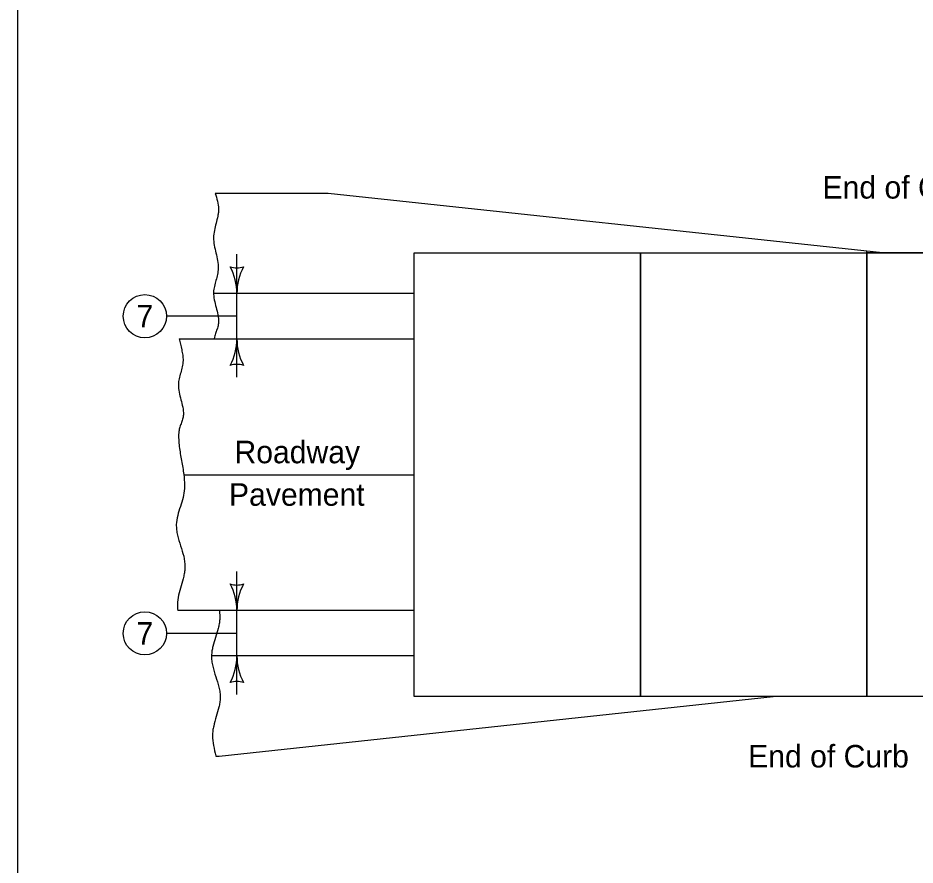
# Model space of a CAD drawing. Extents: x 5546 to 81668, y 3174 to 15999.
# Drawn here: x 17333 to 17970, y 8741 to 9343 of the extents above; entities that cross this region are included whole.
import ezdxf

# ---------------------------------------------------------------- set-up
doc = ezdxf.new("R2010")
doc.units = 0
for name, color, linetype in [('Level 61', 7, 'Continuous'), ('PS_BOLT', 7, 'Continuous'), ('PS_DIM', 7, 'Continuous'), ('Table Border', 7, 'Continuous')]:
    doc.layers.add(name, color=color, linetype=linetype)

msp = doc.modelspace()

# ---------------------------------------------------------------- linework, layer by layer
at = {"layer": 'Level 61'}
msp.add_lwpolyline([(17332.52, 9944.02), (20467.53, 9944.02), (20467.53, 7924.02), (17332.52, 7924.02)], close=True, dxfattribs=at)
at = {"layer": 'PS_DIM'}
for p, q in [((17553, 9217.99), (17472.63, 9217.99)), ((17946.65, 9175.72), (17553, 9217.99)), ((17488.06, 9087.36), (17488.06, 9174.78)), ((17613.88, 9146.9), (17471.46, 9146.9)), ((17458.59, 9130.77), (17438.03, 9130.77)), ((17488.06, 9130.77), (17458.59, 9130.77)), ((17447.13, 9114.73), (17613.88, 9114.73)), ((17450.33, 9018.22), (17613.88, 9018.22)), ((17488.06, 8862.17), (17488.06, 8949.6)), ((17613.88, 8921.71), (17445.98, 8921.71)), ((17458.59, 8905.58), (17438.03, 8905.58)), ((17488.06, 8905.58), (17458.59, 8905.58)), ((17613.88, 8889.54), (17470.02, 8889.54)), ((17475.42, 8818.46), (17868.97, 8860.72))]:
    msp.add_line(p, q, dxfattribs=at)
for points in [[(17613.88, 8860.72), (17613.88, 9175.72), (17774.73, 9175.72), (17774.73, 8860.72)], [(17868.97, 8860.73), (17868.97, 8860.72), (17774.73, 8860.72), (17774.73, 9175.72), (17935.58, 9175.72), (17935.58, 8860.73)], [(17935.58, 8860.73), (17935.58, 9175.72), (17946.65, 9175.72), (17946.65, 9175.72), (18096.43, 9175.72), (18096.43, 8864.74), (18055.7, 8864.74), (18055.7, 8860.73)]]:
    msp.add_lwpolyline(points, close=True, dxfattribs=at)
for centre in [(17422.67, 9130.77), (17422.67, 8905.58)]:
    msp.add_circle(centre, 15.36, dxfattribs=at)
for centre, radius, start, end in [((17488.06, 9180.59), 15.52, 252.26665, 287.73335), ((17447.88, 9146.9), 40.18, 0, 28.07249), ((17528.23, 9146.9), 40.18, 151.92751, 180), ((17447.88, 9114.73), 40.18, 331.92751, 0), ((17528.23, 9114.73), 40.18, 180, 208.07249), ((17488.06, 9081.05), 15.52, 72.26665, 107.73335), ((17488.06, 8955.4), 15.52, 252.26665, 287.73335), ((17447.88, 8921.71), 40.18, 0, 28.07249), ((17528.23, 8921.71), 40.18, 151.92751, 180), ((17447.88, 8889.54), 40.18, 331.92751, 0), ((17528.23, 8889.54), 40.18, 180, 208.07249), ((17488.06, 8855.86), 15.52, 72.26665, 107.73335)]:
    msp.add_arc(centre, radius, start, end, dxfattribs=at)
at = {"layer": 'Table Border'}
for p, q in [((17935.58, 8860.72), (17935.58, 9176.91)), ((17613.88, 8860.72), (17613.88, 9175.72)), ((17613.88, 9175.72), (17774.73, 9175.72)), ((17613.88, 9146.9), (17613.88, 9175.72)), ((17613.88, 9175.72), (17946.65, 9175.72)), ((17774.73, 8860.72), (17774.73, 9175.72)), ((17774.73, 9175.72), (17935.58, 9175.72)), ((18360.8, 9175.72), (17935.58, 9175.72)), ((17613.88, 9114.73), (17613.88, 9146.9)), ((17613.88, 8860.72), (17613.88, 8889.54)), ((18283.22, 8860.73), (17613.88, 8860.73)), ((17868.97, 8860.72), (17613.88, 8860.72)), ((17473.02, 8818.46), (17475.42, 8818.46))]:
    msp.add_line(p, q, dxfattribs=at)
for points in [[(17472.63, 9217.99), (17474.2, 9212.47), (17475.03, 9206.94), (17474.88, 9204.39), (17474.48, 9201.85), (17473.27, 9196.75), (17472.05, 9191.66), (17471.47, 9186.56), (17471.98, 9181.12), (17473.14, 9175.66), (17474.3, 9170.21), (17474.79, 9164.76), (17474.27, 9160.49), (17473.17, 9156.23), (17472.06, 9151.97), (17471.47, 9147.7), (17471.98, 9142.38), (17473.28, 9137.04), (17474.57, 9131.71), (17475.03, 9126.38), (17474.46, 9123.16), (17473.38, 9119.98), (17472.3, 9116.8), (17471.82, 9114.73)], [(17447.13, 9114.73), (17448.85, 9106.96), (17449.54, 9103.07), (17449.79, 9099.2), (17449.26, 9094.92), (17448.17, 9090.66), (17447.05, 9086.4), (17446.47, 9082.14), (17446.98, 9076.82), (17448.28, 9071.48), (17449.57, 9066.14), (17450.02, 9060.81), (17449.46, 9057.59), (17448.38, 9054.41), (17447.29, 9051.23), (17446.71, 9048.02), (17446.71, 9043.11), (17447.14, 9038.17), (17448.72, 9028.22), (17450.33, 9018.27), (17450.86, 9010.88), (17450.82, 9008.44), (17449.79, 9002.02), (17447.88, 8995.61), (17446, 8989.2), (17445.03, 8982.77), (17445.21, 8979.02), (17445.88, 8975.27), (17448.05, 8967.76), (17450.25, 8960.26), (17451.18, 8952.76), (17450.9, 8949.41), (17450.26, 8946.07), (17448.41, 8939.39), (17446.59, 8932.7), (17445.75, 8926), (17445.98, 8921.71)], [(17475.7, 8921.71), (17475.82, 8915.49), (17475.47, 8912.27), (17474.79, 8909.06), (17472.88, 8902.65), (17471, 8896.24), (17470.33, 8893.06), (17470.14, 8891.43), (17470.03, 8889.81), (17470.21, 8886.06), (17470.88, 8882.31), (17473.06, 8874.81), (17475.25, 8867.3), (17475.98, 8863.58), (17476.14, 8861.69), (17476.18, 8859.8), (17475.9, 8856.46), (17475.27, 8853.11), (17473.41, 8846.43), (17471.59, 8839.74), (17470.95, 8836.41), (17470.81, 8834.72), (17470.76, 8833.04), (17471.45, 8825.84), (17472.99, 8818.6), (17473.02, 8818.46)]]:
    msp.add_spline(points, degree=3, dxfattribs=at)

# ---------------------------------------------------------------- texts
at = {"layer": 'PS_BOLT'}
for s, p in [('End of Curb', (17904.03, 9214.28)), ('7', (17416.78, 9122.77)), ('Roadway', (17486.34, 9026.35)), ('Pavement', (17482.45, 8996.17)), ('7', (17416.78, 8897.58)), ('End of Curb', (17851.21, 8810.33))]:
    msp.add_text(s, height=16, dxfattribs=at).set_placement(p)

doc.saveas('drawing.dxf')
